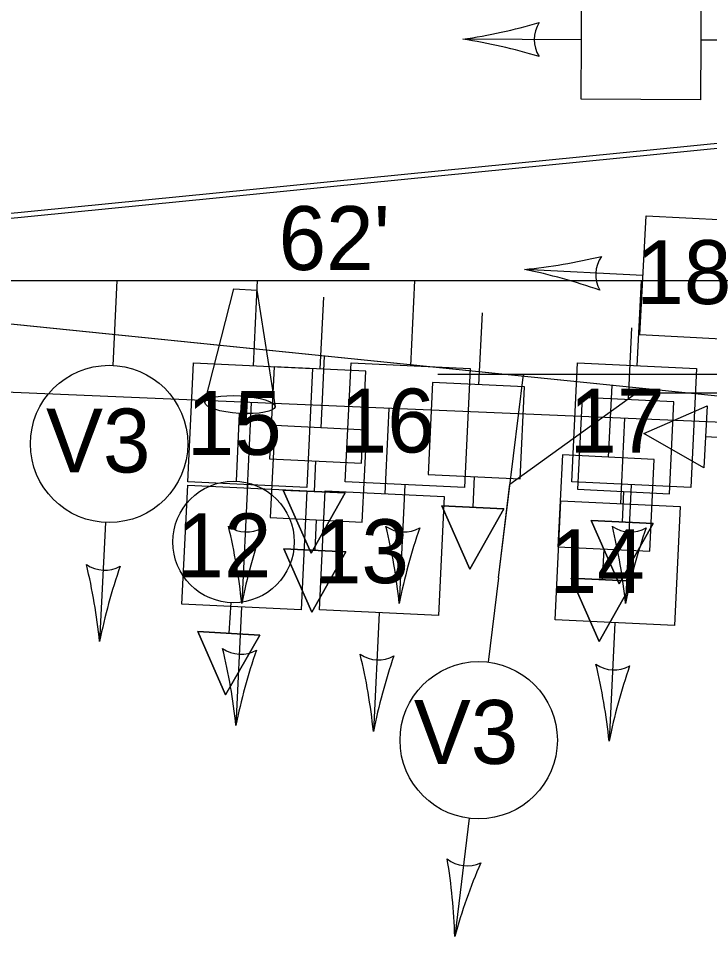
# Model space of a CAD drawing. Extents: x 647787 to 668496, y 640478 to 654412.
# Drawn here: x 659900.71 to 659935.86, y 647461.33 to 647508.04 of the extents above; entities that cross this region are included whole.
import ezdxf

# ---------------------------------------------------------------- set-up
doc = ezdxf.new("R2010")
doc.units = 0
for name, color, linetype in [('T_EXIST SIGNAL HEAD', 7, 'Continuous'), ('TEMP_SIGNAL POLES', 7, 'Continuous'), ('TEMP_SIGNAL_HEAD_STAGE 1A', 7, 'Continuous'), ('TEMP_SIGNAL_HEAD_STAGE 2', 7, 'Continuous'), ('TEMP_SIGNAL_HEAD_STAGE 2 SALEM', 7, 'Continuous'), ('TEMP_SIGNAL_HEAD_Stage 3', 7, 'Continuous'), ('TEMP_SIGNAL_HEAD_STAGE 5', 7, 'Continuous'), ('TEMP_SIGNAL_POLES_STAGE 1A', 7, 'Continuous'), ('TEMP_SIGNAL_POLES_STAGE 2', 7, 'Continuous'), ('TEMP_SIGNAL_POLES_STAGE 3', 7, 'Continuous'), ('TEMP_SIGNAL_POLES_STAGE 5', 7, 'Continuous'), ('TEXT_TEMP_SIGNAL_POLES_STAGE 2', 7, 'Continuous'), ('TEXT_TEMP_SIGNAL_POLES_STAGE 3', 7, 'Continuous'), ('TEXT_TEMP_SIGNAL_POLES_STAGE 4', 7, 'Continuous'), ('TEXT_TEMP_SIGNAL_POLES_STAGE 5', 7, 'Continuous')]:
    doc.layers.add(name, color=color, linetype=linetype)

msp = doc.modelspace()

# ---------------------------------------------------------------- linework, layer by layer
at = {"layer": 'T_EXIST SIGNAL HEAD'}
for points in [[(659910.19, 647488.503), (659911.67, 647494.293)], [(659910.19, 647488.503), (659911.67, 647494.293)], [(659911.67, 647494.293), (659912.835, 647494.224)], [(659911.67, 647494.293), (659912.835, 647494.224)], [(659912.835, 647494.224), (659913.766, 647488.291)], [(659912.835, 647494.224), (659913.766, 647488.291)], [(659916.221, 647493.863), (659916.046, 647490.21)], [(659916.221, 647493.863), (659916.046, 647490.21)], [(659916.221, 647493.863), (659916.046, 647490.21)], [(659916.221, 647493.863), (659916.046, 647490.21)], [(659924.287, 647493.06), (659924.112, 647489.407)], [(659924.287, 647493.06), (659924.112, 647489.407)], [(659924.287, 647493.06), (659924.112, 647489.407)], [(659924.287, 647493.06), (659924.112, 647489.407)], [(659931.887, 647492.304), (659931.712, 647488.651)], [(659931.887, 647492.304), (659931.712, 647488.651)], [(659931.887, 647492.304), (659931.712, 647488.651)], [(659931.887, 647492.304), (659931.712, 647488.651)], [(659911.795, 647484.495), (659911.957, 647487.951)], [(659911.795, 647484.495), (659911.957, 647487.951)], [(659915.823, 647485.535), (659915.748, 647483.977)], [(659915.823, 647485.535), (659915.748, 647483.977)], [(659915.823, 647485.535), (659915.748, 647483.977)], [(659915.823, 647485.535), (659915.748, 647483.977)], [(659923.889, 647484.733), (659923.814, 647483.174)], [(659923.889, 647484.733), (659923.814, 647483.174)], [(659923.889, 647484.733), (659923.814, 647483.174)], [(659923.889, 647484.733), (659923.814, 647483.174)], [(659914.172, 647484.052), (659917.325, 647483.901), (659915.598, 647480.836), (659914.172, 647484.052)], [(659914.172, 647484.052), (659917.325, 647483.901), (659915.598, 647480.836), (659914.172, 647484.052)], [(659914.172, 647484.052), (659917.325, 647483.901), (659915.598, 647480.836), (659914.172, 647484.052)], [(659914.172, 647484.052), (659917.325, 647483.901), (659915.598, 647480.836), (659914.172, 647484.052)], [(659931.488, 647483.977), (659931.414, 647482.418)], [(659931.488, 647483.977), (659931.414, 647482.418)], [(659931.488, 647483.977), (659931.414, 647482.418)], [(659931.488, 647483.977), (659931.414, 647482.418)], [(659922.238, 647483.25), (659925.391, 647483.099), (659923.664, 647480.033), (659922.238, 647483.25)], [(659922.238, 647483.25), (659925.391, 647483.099), (659923.664, 647480.033), (659922.238, 647483.25)], [(659922.238, 647483.25), (659925.391, 647483.099), (659923.664, 647480.033), (659922.238, 647483.25)], [(659922.238, 647483.25), (659925.391, 647483.099), (659923.664, 647480.033), (659922.238, 647483.25)], [(659929.837, 647482.494), (659932.99, 647482.343), (659931.263, 647479.277), (659929.837, 647482.494)], [(659929.837, 647482.494), (659932.99, 647482.343), (659931.263, 647479.277), (659929.837, 647482.494)], [(659929.837, 647482.494), (659932.99, 647482.343), (659931.263, 647479.277), (659929.837, 647482.494)], [(659929.837, 647482.494), (659932.99, 647482.343), (659931.263, 647479.277), (659929.837, 647482.494)], [(659911.506, 647478.324), (659911.415, 647476.766)], [(659911.506, 647478.324), (659911.415, 647476.766)], [(659909.84, 647476.858), (659912.991, 647476.675), (659911.233, 647473.627), (659909.84, 647476.858)], [(659909.84, 647476.858), (659912.991, 647476.675), (659911.233, 647473.627), (659909.84, 647476.858)]]:
    msp.add_lwpolyline(points, dxfattribs=at)
for points in [[(659918.384, 647490.098), (659913.709, 647490.322), (659913.485, 647485.647), (659918.16, 647485.423)], [(659918.384, 647490.098), (659913.709, 647490.322), (659913.485, 647485.647), (659918.16, 647485.423)], [(659918.384, 647490.098), (659913.709, 647490.322), (659913.485, 647485.647), (659918.16, 647485.423)], [(659918.384, 647490.098), (659913.709, 647490.322), (659913.485, 647485.647), (659918.16, 647485.423)], [(659926.45, 647489.295), (659921.775, 647489.519), (659921.551, 647484.844), (659926.226, 647484.621)], [(659926.45, 647489.295), (659921.775, 647489.519), (659921.551, 647484.844), (659926.226, 647484.621)], [(659926.45, 647489.295), (659921.775, 647489.519), (659921.551, 647484.844), (659926.226, 647484.621)], [(659926.45, 647489.295), (659921.775, 647489.519), (659921.551, 647484.844), (659926.226, 647484.621)], [(659934.049, 647488.539), (659929.375, 647488.763), (659929.151, 647484.089), (659933.826, 647483.865)], [(659934.049, 647488.539), (659929.375, 647488.763), (659929.151, 647484.089), (659933.826, 647483.865)], [(659934.049, 647488.539), (659929.375, 647488.763), (659929.151, 647484.089), (659933.826, 647483.865)], [(659934.049, 647488.539), (659929.375, 647488.763), (659929.151, 647484.089), (659933.826, 647483.865)], [(659915.598, 647480.836), (659917.325, 647483.901), (659914.172, 647484.052)], [(659915.598, 647480.836), (659917.325, 647483.901), (659914.172, 647484.052)], [(659915.598, 647480.836), (659917.325, 647483.901), (659914.172, 647484.052)], [(659915.598, 647480.836), (659917.325, 647483.901), (659914.172, 647484.052)], [(659923.664, 647480.033), (659925.391, 647483.099), (659922.238, 647483.25)], [(659923.664, 647480.033), (659925.391, 647483.099), (659922.238, 647483.25)], [(659923.664, 647480.033), (659925.391, 647483.099), (659922.238, 647483.25)], [(659923.664, 647480.033), (659925.391, 647483.099), (659922.238, 647483.25)], [(659931.263, 647479.277), (659932.99, 647482.343), (659929.837, 647482.494)], [(659931.263, 647479.277), (659932.99, 647482.343), (659929.837, 647482.494)], [(659931.263, 647479.277), (659932.99, 647482.343), (659929.837, 647482.494)], [(659931.263, 647479.277), (659932.99, 647482.343), (659929.837, 647482.494)], [(659911.233, 647473.627), (659912.991, 647476.675), (659909.84, 647476.858)], [(659911.233, 647473.627), (659912.991, 647476.675), (659909.84, 647476.858)]]:
    msp.add_lwpolyline(points, close=True, dxfattribs=at)
msp.add_circle((659911.65, 647481.409), 3.089, dxfattribs=at)
msp.add_circle((659911.65, 647481.409), 3.089, dxfattribs=at)
msp.add_ellipse((659911.978, 647488.397), major_axis=(1.788, -0.106), ratio=0.249111, dxfattribs=at)
msp.add_ellipse((659911.978, 647488.397), major_axis=(1.788, -0.106), ratio=0.249111, dxfattribs=at)
at = {"layer": 'TEMP_SIGNAL POLES'}
for p, q in [((659958.313, 647486.584), (659859.629, 647496.632)), ((659958.313, 647486.584), (659859.629, 647496.632)), ((659958.313, 647486.584), (659859.629, 647496.632)), ((659958.316, 647486.586), (659859.631, 647496.634))]:
    msp.add_line(p, q, dxfattribs=at)
at = {"layer": 'TEMP_SIGNAL_HEAD_STAGE 1A'}
for p, q in [((659866.35, 647494.527), (659956.028, 647503.397)), ((659866.35, 647494.527), (659956.028, 647503.397)), ((659866.35, 647494.527), (659956.028, 647503.397)), ((659866.351, 647494.778), (659955.801, 647503.625)), ((659866.351, 647494.778), (659955.801, 647503.625)), ((659866.351, 647494.778), (659955.801, 647503.625))]:
    msp.add_line(p, q, dxfattribs=at)
at = {"layer": 'TEMP_SIGNAL_HEAD_STAGE 2'}
for p, q in [((659932.474, 647494.966), (659926.441, 647495.272)), ((659947.041, 647489.927), (659922.041, 647489.927)), ((659925.128, 647479.594), (659926.389, 647489.927)), ((659912.555, 647488.502), (659912.348, 647484.16)), ((659919.549, 647488.207), (659919.341, 647483.865)), ((659931.539, 647487.703), (659931.331, 647483.361)), ((659925.128, 647479.594), (659924.603, 647475.296)), ((659912.058, 647478.104), (659911.77, 647472.07)), ((659919.052, 647477.809), (659918.764, 647471.776)), ((659931.042, 647477.304), (659930.753, 647471.271)), ((659923.634, 647467.355), (659922.899, 647461.335))]:
    msp.add_line(p, q, dxfattribs=at)
for points in [[(659938.683, 647497.687), (659938.376, 647491.631), (659932.321, 647491.938), (659932.628, 647497.995)], [(659909.319, 647484.305), (659915.376, 647484.015), (659915.087, 647477.959), (659909.029, 647478.249)], [(659916.313, 647484.01), (659922.37, 647483.721), (659922.081, 647477.665), (659916.023, 647477.954)], [(659928.302, 647483.505), (659934.36, 647483.216), (659934.071, 647477.16), (659928.013, 647477.449)]]:
    msp.add_lwpolyline(points, close=True, dxfattribs=at)
msp.add_circle((659924.119, 647471.325), 4, dxfattribs=at)
for centre, radius, start, end in [((659923.512, 647524.599), 29.472, 275.7037, 283.4418), ((659931.701, 647495.006), 1.629, 145.2481, 208.9427), ((659920.559, 647466.394), 29.472, 70.749, 78.4871), ((659912.021, 647477.331), 1.629, 235.4173, 299.1119), ((659882.452, 647469.054), 29.472, 5.8729, 13.611), ((659940.666, 647466.273), 29.472, 160.9182, 168.6563), ((659919.014, 647477.036), 1.629, 235.4173, 299.1119), ((659889.446, 647468.76), 29.472, 5.8729, 13.611), ((659947.659, 647465.979), 29.472, 160.9182, 168.6563), ((659931.004, 647476.531), 1.629, 235.4173, 299.1119), ((659901.435, 647468.255), 29.472, 5.8729, 13.611), ((659959.649, 647465.474), 29.472, 160.9182, 168.6563), ((659923.537, 647466.563), 1.629, 231.1951, 294.8897), ((659893.44, 647460.48), 29.472, 1.6617, 9.3999), ((659951.29, 647453.432), 29.47, 156.7061, 164.4442)]:
    msp.add_arc(centre, radius, start, end, dxfattribs=at)
at = {"layer": 'TEMP_SIGNAL_HEAD_STAGE 2 SALEM'}
for points in [[(659916.267, 647490.865), (659916.088, 647487.213)], [(659916.267, 647490.865), (659916.088, 647487.213)], [(659916.267, 647490.865), (659916.088, 647487.213)], [(659916.267, 647490.865), (659916.088, 647487.213)], [(659930.891, 647489.377), (659930.711, 647485.724)], [(659930.891, 647489.377), (659930.711, 647485.724)], [(659930.891, 647489.377), (659930.711, 647485.724)], [(659930.891, 647489.377), (659930.711, 647485.724)], [(659937.211, 647486.681), (659935.653, 647486.761)], [(659937.211, 647486.681), (659935.653, 647486.761)], [(659915.858, 647482.538), (659915.781, 647480.98)], [(659915.858, 647482.538), (659915.781, 647480.98)], [(659915.858, 647482.538), (659915.781, 647480.98)], [(659915.858, 647482.538), (659915.781, 647480.98)], [(659914.205, 647481.058), (659917.357, 647480.903), (659915.626, 647477.839), (659914.205, 647481.058)], [(659914.205, 647481.058), (659917.357, 647480.903), (659915.626, 647477.839), (659914.205, 647481.058)], [(659914.205, 647481.058), (659917.357, 647480.903), (659915.626, 647477.839), (659914.205, 647481.058)], [(659914.205, 647481.058), (659917.357, 647480.903), (659915.626, 647477.839), (659914.205, 647481.058)], [(659930.481, 647481.05), (659930.404, 647479.491)], [(659930.481, 647481.05), (659930.404, 647479.491)], [(659930.481, 647481.05), (659930.404, 647479.491)], [(659930.481, 647481.05), (659930.404, 647479.491)], [(659928.828, 647479.569), (659931.981, 647479.414), (659930.25, 647476.35), (659928.828, 647479.569)], [(659928.828, 647479.569), (659931.981, 647479.414), (659930.25, 647476.35), (659928.828, 647479.569)], [(659928.828, 647479.569), (659931.981, 647479.414), (659930.25, 647476.35), (659928.828, 647479.569)], [(659928.828, 647479.569), (659931.981, 647479.414), (659930.25, 647476.35), (659928.828, 647479.569)]]:
    msp.add_lwpolyline(points, dxfattribs=at)
for points in [[(659932.512, 647486.921), (659935.734, 647488.337), (659935.573, 647485.184)], [(659932.512, 647486.921), (659935.734, 647488.337), (659935.573, 647485.184)], [(659918.425, 647487.098), (659913.75, 647487.328), (659913.52, 647482.653), (659918.195, 647482.423)], [(659918.425, 647487.098), (659913.75, 647487.328), (659913.52, 647482.653), (659918.195, 647482.423)], [(659918.425, 647487.098), (659913.75, 647487.328), (659913.52, 647482.653), (659918.195, 647482.423)], [(659918.425, 647487.098), (659913.75, 647487.328), (659913.52, 647482.653), (659918.195, 647482.423)], [(659933.048, 647485.609), (659928.374, 647485.839), (659928.144, 647481.165), (659932.818, 647480.934)], [(659933.048, 647485.609), (659928.374, 647485.839), (659928.144, 647481.165), (659932.818, 647480.934)], [(659933.048, 647485.609), (659928.374, 647485.839), (659928.144, 647481.165), (659932.818, 647480.934)], [(659933.048, 647485.609), (659928.374, 647485.839), (659928.144, 647481.165), (659932.818, 647480.934)], [(659915.626, 647477.839), (659917.357, 647480.903), (659914.205, 647481.058)], [(659915.626, 647477.839), (659917.357, 647480.903), (659914.205, 647481.058)], [(659915.626, 647477.839), (659917.357, 647480.903), (659914.205, 647481.058)], [(659915.626, 647477.839), (659917.357, 647480.903), (659914.205, 647481.058)], [(659930.25, 647476.35), (659931.981, 647479.414), (659928.828, 647479.569)], [(659930.25, 647476.35), (659931.981, 647479.414), (659928.828, 647479.569)], [(659930.25, 647476.35), (659931.981, 647479.414), (659928.828, 647479.569)], [(659930.25, 647476.35), (659931.981, 647479.414), (659928.828, 647479.569)]]:
    msp.add_lwpolyline(points, close=True, dxfattribs=at)
at = {"layer": 'TEMP_SIGNAL_HEAD_Stage 3'}
for p, q in [((659925.708, 647484.347), (659932.141, 647488.991)), ((659932.141, 647488.991), (659957.141, 647488.991)), ((659912.555, 647488.502), (659912.348, 647484.16)), ((659919.549, 647488.207), (659919.341, 647483.865)), ((659931.539, 647487.703), (659931.331, 647483.361)), ((659925.128, 647479.594), (659925.708, 647484.347)), ((659925.128, 647479.594), (659924.603, 647475.296)), ((659912.058, 647478.104), (659911.77, 647472.07)), ((659919.052, 647477.809), (659918.764, 647471.776)), ((659931.042, 647477.304), (659930.753, 647471.271)), ((659923.634, 647467.355), (659922.899, 647461.335))]:
    msp.add_line(p, q, dxfattribs=at)
for points in [[(659909.319, 647484.305), (659915.376, 647484.015), (659915.087, 647477.959), (659909.029, 647478.249)], [(659916.313, 647484.01), (659922.37, 647483.721), (659922.081, 647477.665), (659916.023, 647477.954)], [(659928.302, 647483.505), (659934.36, 647483.216), (659934.071, 647477.16), (659928.013, 647477.449)]]:
    msp.add_lwpolyline(points, close=True, dxfattribs=at)
msp.add_circle((659924.119, 647471.325), 4, dxfattribs=at)
for centre, radius, start, end in [((659912.021, 647477.331), 1.629, 235.4173, 299.1119), ((659882.452, 647469.054), 29.472, 5.8729, 13.611), ((659940.666, 647466.273), 29.472, 160.9182, 168.6563), ((659919.014, 647477.036), 1.629, 235.4173, 299.1119), ((659889.446, 647468.76), 29.472, 5.8729, 13.611), ((659947.659, 647465.979), 29.472, 160.9182, 168.6563), ((659931.004, 647476.531), 1.629, 235.4173, 299.1119), ((659901.435, 647468.255), 29.472, 5.8729, 13.611), ((659959.649, 647465.474), 29.472, 160.9182, 168.6563), ((659923.537, 647466.563), 1.629, 231.1951, 294.8897), ((659893.44, 647460.48), 29.472, 1.6617, 9.3999), ((659951.29, 647453.432), 29.47, 156.7061, 164.4442)]:
    msp.add_arc(centre, radius, start, end, dxfattribs=at)
at = {"layer": 'TEMP_SIGNAL_HEAD_STAGE 5'}
for p, q in [((659905.72, 647494.718), (659905.513, 647490.392)), ((659905.72, 647494.718), (659905.513, 647490.392)), ((659912.852, 647494.718), (659912.645, 647490.375)), ((659912.852, 647494.718), (659912.645, 647490.375)), ((659920.861, 647494.718), (659920.654, 647490.375)), ((659920.861, 647494.718), (659920.654, 647490.375)), ((659932.374, 647494.718), (659932.167, 647490.375)), ((659932.374, 647494.718), (659932.167, 647490.375)), ((659912.355, 647484.319), (659912.067, 647478.286)), ((659912.355, 647484.319), (659912.067, 647478.286)), ((659920.364, 647484.319), (659920.076, 647478.286)), ((659920.364, 647484.319), (659920.076, 647478.286)), ((659931.877, 647484.319), (659931.589, 647478.286)), ((659931.877, 647484.319), (659931.589, 647478.286)), ((659905.131, 647482.401), (659904.841, 647476.344)), ((659905.131, 647482.401), (659904.841, 647476.344))]:
    msp.add_line(p, q, dxfattribs=at)
for points in [[(659909.616, 647490.52), (659915.673, 647490.231), (659915.384, 647484.175), (659909.326, 647484.464)], [(659909.616, 647490.52), (659915.673, 647490.231), (659915.384, 647484.175), (659909.326, 647484.464)], [(659917.625, 647490.52), (659923.683, 647490.231), (659923.393, 647484.175), (659917.335, 647484.464)], [(659917.625, 647490.52), (659923.683, 647490.231), (659923.393, 647484.175), (659917.335, 647484.464)], [(659929.138, 647490.52), (659935.196, 647490.231), (659934.906, 647484.175), (659928.849, 647484.464)], [(659929.138, 647490.52), (659935.196, 647490.231), (659934.906, 647484.175), (659928.849, 647484.464)]]:
    msp.add_lwpolyline(points, close=True, dxfattribs=at)
msp.add_circle((659905.322, 647486.397), 4, dxfattribs=at)
msp.add_circle((659905.322, 647486.397), 4, dxfattribs=at)
for centre, radius, start, end in [((659912.317, 647483.546), 1.629, 235.4157, 299.1103), ((659882.748, 647475.271), 29.472, 5.8713, 13.6095), ((659912.317, 647483.546), 1.629, 235.4157, 299.1103), ((659882.748, 647475.271), 29.472, 5.8713, 13.6095), ((659920.327, 647483.546), 1.629, 235.4157, 299.1103), ((659890.758, 647475.271), 29.472, 5.8713, 13.6095), ((659920.327, 647483.546), 1.629, 235.4157, 299.1103), ((659890.758, 647475.271), 29.472, 5.8713, 13.6095), ((659931.84, 647483.546), 1.629, 235.4157, 299.1103), ((659902.271, 647475.271), 29.472, 5.8713, 13.6095), ((659931.84, 647483.546), 1.629, 235.4157, 299.1103), ((659902.271, 647475.271), 29.472, 5.8713, 13.6095), ((659940.962, 647472.488), 29.472, 160.9166, 168.6547), ((659940.962, 647472.488), 29.472, 160.9166, 168.6547), ((659948.971, 647472.488), 29.472, 160.9166, 168.6547), ((659948.971, 647472.488), 29.472, 160.9166, 168.6547), ((659960.484, 647472.488), 29.472, 160.9166, 168.6547), ((659960.484, 647472.488), 29.472, 160.9166, 168.6547), ((659905.092, 647481.604), 1.629, 235.4131, 299.1077), ((659875.524, 647473.324), 29.472, 5.8797, 13.6179), ((659905.092, 647481.604), 1.629, 235.4131, 299.1077), ((659875.524, 647473.324), 29.472, 5.8797, 13.6179), ((659933.736, 647470.55), 29.47, 160.9241, 168.6622), ((659933.736, 647470.55), 29.47, 160.9241, 168.6622)]:
    msp.add_arc(centre, radius, start, end, dxfattribs=at)
at = {"layer": 'TEMP_SIGNAL_POLES_STAGE 1A'}
for p, q in [((659929.349, 647506.958), (659923.309, 647506.982)), ((659939.759, 647506.915), (659935.412, 647506.933)), ((659892.993, 647494.718), (659954.993, 647494.718)), ((659905.72, 647494.718), (659905.513, 647490.392)), ((659912.852, 647494.718), (659912.645, 647490.375)), ((659920.861, 647494.718), (659920.654, 647490.375)), ((659932.374, 647494.718), (659932.167, 647490.375)), ((659912.355, 647484.319), (659912.067, 647478.286)), ((659920.364, 647484.319), (659920.076, 647478.286)), ((659931.877, 647484.319), (659931.589, 647478.286)), ((659905.131, 647482.401), (659904.841, 647476.344))]:
    msp.add_line(p, q, dxfattribs=at)
for points in [[(659935.425, 647509.965), (659935.4, 647503.901), (659929.337, 647503.925), (659929.362, 647509.99)], [(659909.616, 647490.52), (659915.673, 647490.231), (659915.384, 647484.175), (659909.326, 647484.464)], [(659917.625, 647490.52), (659923.683, 647490.231), (659923.393, 647484.175), (659917.335, 647484.464)], [(659929.138, 647490.52), (659935.196, 647490.231), (659934.906, 647484.175), (659928.849, 647484.464)]]:
    msp.add_lwpolyline(points, close=True, dxfattribs=at)
msp.add_circle((659905.322, 647486.397), 4, dxfattribs=at)
for centre, radius, start, end in [((659919.016, 647536.141), 29.472, 278.3758, 286.1139), ((659928.575, 647506.962), 1.629, 147.9202, 211.6148), ((659918.779, 647477.861), 29.472, 73.421, 81.1592), ((659912.317, 647483.546), 1.629, 235.4157, 299.1103), ((659882.748, 647475.271), 29.472, 5.8713, 13.6095), ((659920.327, 647483.546), 1.629, 235.4157, 299.1103), ((659890.758, 647475.271), 29.472, 5.8713, 13.6095), ((659931.84, 647483.546), 1.629, 235.4157, 299.1103), ((659902.271, 647475.271), 29.472, 5.8713, 13.6095), ((659940.962, 647472.488), 29.472, 160.9166, 168.6547), ((659948.971, 647472.488), 29.472, 160.9166, 168.6547), ((659960.484, 647472.488), 29.472, 160.9166, 168.6547), ((659905.092, 647481.604), 1.629, 235.4131, 299.1077), ((659875.524, 647473.324), 29.472, 5.8797, 13.6179), ((659933.736, 647470.55), 29.47, 160.9241, 168.6622)]:
    msp.add_arc(centre, radius, start, end, dxfattribs=at)
at = {"layer": 'TEMP_SIGNAL_POLES_STAGE 2'}
msp.add_line((659959.035, 647486.545), (659836.648, 647491.699), dxfattribs=at)
at = {"layer": 'TEMP_SIGNAL_POLES_STAGE 3'}
msp.add_line((659959.035, 647486.545), (659836.648, 647491.699), dxfattribs=at)
at = {"layer": 'TEMP_SIGNAL_POLES_STAGE 5'}
msp.add_line((659892.993, 647494.718), (659954.993, 647494.718), dxfattribs=at)
msp.add_line((659892.993, 647494.718), (659954.993, 647494.718), dxfattribs=at)

# ---------------------------------------------------------------- texts
at = {"layer": 'TEXT_TEMP_SIGNAL_POLES_STAGE 2'}
for s, p in [('18', (659932.133, 647493.511)), ('12', (659908.743, 647479.609)), ('13', (659915.737, 647479.314)), ('14', (659927.727, 647478.809))]:
    msp.add_text(s, height=3.25, dxfattribs=at).set_placement(p)
msp.add_text('V3', height=3.25, rotation=359.934, dxfattribs=at).set_placement((659920.815, 647470.124))
at = {"layer": 'TEXT_TEMP_SIGNAL_POLES_STAGE 3'}
for s, p in [('12', (659908.743, 647479.609)), ('13', (659915.737, 647479.314)), ('14', (659927.727, 647478.809))]:
    msp.add_text(s, height=3.25, dxfattribs=at).set_placement(p)
msp.add_text('V3', height=3.25, rotation=359.934, dxfattribs=at).set_placement((659920.815, 647470.124))
at = {"layer": 'TEXT_TEMP_SIGNAL_POLES_STAGE 4'}
for s, p in [("62'", (659913.943, 647495.243)), ('16', (659917.051, 647485.96)), ('15', (659909.266, 647485.838)), ('17', (659928.734, 647485.954))]:
    msp.add_text(s, height=3.25, dxfattribs=at).set_placement(p)
msp.add_text('V3', height=3.25, rotation=359.934, dxfattribs=at).set_placement((659902.11, 647484.949))
at = {"layer": 'TEXT_TEMP_SIGNAL_POLES_STAGE 5'}
for s, p in [("62'", (659913.943, 647495.243)), ('16', (659917.051, 647485.96)), ('15', (659909.266, 647485.838)), ('17', (659928.734, 647485.954))]:
    msp.add_text(s, height=3.25, dxfattribs=at).set_placement(p)
msp.add_text('V3', height=3.25, rotation=359.934, dxfattribs=at).set_placement((659902.11, 647484.949))

doc.saveas('drawing.dxf')
